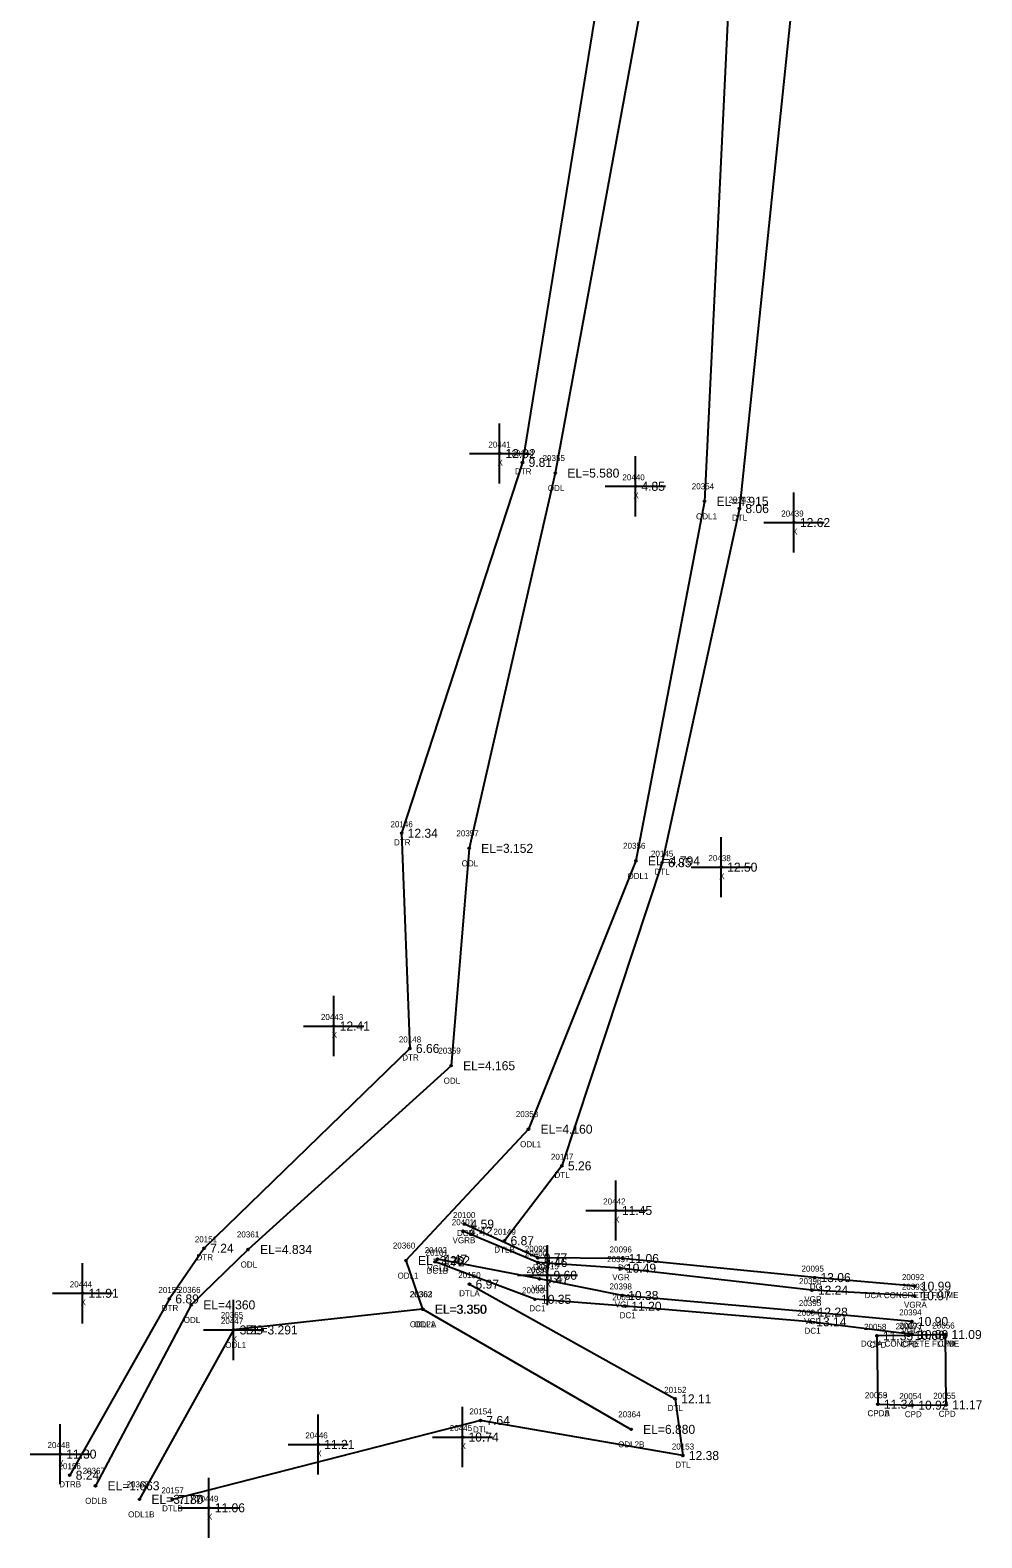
# Model space of a CAD drawing. Extents: x 2072302 to 2072980, y 127650 to 129736.
# Drawn here: x 2072301.6 to 2072459.9, y 128065.3 to 128316.1 of the extents above; entities that cross this region are included whole.
import ezdxf

# ---------------------------------------------------------------- set-up
doc = ezdxf.new("R2010")
doc.units = 0
for name, color, linetype in [('RD_EX_Conc', 7, 'Continuous'), ('RD_EX_Conc_txCode', 7, 'Continuous'), ('RD_EX_H2O', 7, 'Continuous'), ('RD_EX_H2O_txCode', 7, 'Continuous'), ('RD_EX_Misc', 7, 'Continuous'), ('RD_EX_Misc_txCode', 7, 'Continuous'), ('RD_EX_Road', 7, 'Continuous'), ('RD_EX_Road_txCode', 7, 'Continuous'), ('RD_EX_TX_Conc_ELEV', 7, 'Continuous'), ('RD_EX_TX_H2O_ELEV', 7, 'Continuous'), ('RD_EX_TX_Misc_ELEV', 7, 'Continuous'), ('RD_EX_TX_Road_ELEV', 7, 'Continuous'), ('RD_SMD_Locator', 7, 'Continuous')]:
    doc.layers.add(name, color=color, linetype=linetype)

msp = doc.modelspace()

# ---------------------------------------------------------------- linework, layer by layer
at = {"layer": 'RD_EX_Conc'}
for points in [[(2072448.74, 128107.16), (2072432.05, 128108.58), (2072400.16, 128111.76), (2072386.04, 128111.87), (2072373.86, 128117.48)], [(2072448.27, 128099.1), (2072431.34, 128101.24), (2072400.6, 128103.82), (2072385.58, 128104.97), (2072368.98, 128111.22)], [(2072442.59, 128087.52), (2072448.31, 128087.36), (2072453.95, 128087.42), (2072453.82, 128099.11), (2072447.69, 128098.97), (2072442.43, 128098.89), (2072442.59, 128087.52)]]:
    msp.add_lwpolyline(points, dxfattribs=at)
at = {"layer": 'RD_EX_H2O'}
msp.add_line((2072366.96, 128103.32), (2072401.56, 128083.34), dxfattribs=at)
for points in [[(2072402.16, 128559.26), (2072408.19, 128460.51), (2072419.68, 128361.12), (2072413.76, 128237.7), (2072402.36, 128177.9), (2072384.5, 128133.27), (2072364.13, 128111.41), (2072366.88, 128103.31), (2072335.48, 128099.87), (2072319.81, 128071.7)], [(2072403.62, 128560.29), (2072411.45, 128462.26), (2072432.66, 128362.62), (2072419.56, 128236.49), (2072406.7, 128177.6), (2072390.06, 128127.17), (2072380.51, 128114.72)], [(2072394.05, 128557.65), (2072400.51, 128459.22), (2072402.07, 128358.79), (2072383.51, 128244.18), (2072363.41, 128182.49), (2072364.78, 128146.69), (2072330.57, 128113.46), (2072324.79, 128105.03), (2072308.22, 128075.71)], [(2072398.39, 128558.24), (2072402.78, 128459.46), (2072410.6, 128360.44), (2072388.96, 128242.4), (2072374.63, 128179.98), (2072371.63, 128143.83), (2072337.87, 128113.26), (2072328.43, 128104.04), (2072312.51, 128073.95)], [(2072374.7, 128107.49), (2072408.89, 128088.41), (2072410.16, 128078.98), (2072376.5, 128084.82), (2072325.3, 128071.69)]]:
    msp.add_lwpolyline(points, dxfattribs=at)
at = {"layer": 'RD_EX_Misc'}
for p, q in [((2072379.67, 128240.64), (2072379.67, 128250.64)), ((2072374.67, 128245.64), (2072384.67, 128245.64)), ((2072402.27, 128235.2), (2072402.27, 128245.2)), ((2072397.27, 128240.2), (2072407.27, 128240.2)), ((2072428.63, 128229.17), (2072428.63, 128239.17)), ((2072423.63, 128234.17), (2072433.63, 128234.17)), ((2072416.53, 128171.85), (2072416.53, 128181.85)), ((2072411.53, 128176.85), (2072421.53, 128176.85)), ((2072352.11, 128145.43), (2072352.11, 128155.43)), ((2072347.11, 128150.43), (2072357.11, 128150.43)), ((2072399.04, 128114.74), (2072399.04, 128124.74)), ((2072394.04, 128119.74), (2072404.04, 128119.74)), ((2072387.66, 128103.97), (2072387.66, 128113.97)), ((2072310.34, 128100.97), (2072310.34, 128110.97)), ((2072382.66, 128108.97), (2072392.66, 128108.97)), ((2072305.34, 128105.97), (2072315.34, 128105.97)), ((2072335.48, 128094.87), (2072335.48, 128104.87)), ((2072330.48, 128099.87), (2072340.48, 128099.87)), ((2072349.54, 128075.83), (2072349.54, 128085.83)), ((2072373.53, 128077.06), (2072373.53, 128087.06)), ((2072306.65, 128074.22), (2072306.65, 128084.22)), ((2072344.54, 128080.83), (2072354.54, 128080.83)), ((2072368.53, 128082.06), (2072378.53, 128082.06)), ((2072301.65, 128079.22), (2072311.65, 128079.22)), ((2072331.34, 128065.29), (2072331.34, 128075.29)), ((2072326.34, 128070.29), (2072336.34, 128070.29))]:
    msp.add_line(p, q, dxfattribs=at)
at = {"layer": 'RD_EX_Road'}
for points in [[(2072448.68, 128105.56), (2072431.62, 128106.49), (2072399.7, 128110.15), (2072386.07, 128111.1), (2072373.61, 128116.3)], [(2072448.25, 128101.29), (2072431.57, 128102.84), (2072400.08, 128105.61), (2072386.32, 128108.37), (2072369.39, 128111.65)]]:
    msp.add_lwpolyline(points, dxfattribs=at)
at = {"layer": 'RD_SMD_Locator'}
for centre in [(2072379.67, 128245.64), (2072383.51, 128244.18), (2072388.96, 128242.4), (2072402.27, 128240.2), (2072413.76, 128237.7), (2072419.56, 128236.49), (2072428.63, 128234.17), (2072363.41, 128182.49), (2072374.63, 128179.98), (2072402.36, 128177.9), (2072406.7, 128177.6), (2072416.53, 128176.85), (2072352.11, 128150.43), (2072364.78, 128146.69), (2072371.63, 128143.83), (2072384.5, 128133.27), (2072390.06, 128127.17), (2072399.04, 128119.74), (2072373.86, 128117.48), (2072373.61, 128116.3), (2072380.51, 128114.72), (2072330.57, 128113.46), (2072337.87, 128113.26), (2072364.13, 128111.41), (2072368.98, 128111.22), (2072369.39, 128111.65), (2072386.04, 128111.87), (2072386.07, 128111.1), (2072399.7, 128110.15), (2072400.16, 128111.76), (2072374.7, 128107.49), (2072386.32, 128108.37), (2072387.66, 128108.97), (2072432.05, 128108.58), (2072448.74, 128107.16), (2072310.34, 128105.97), (2072324.79, 128105.03), (2072385.58, 128104.97), (2072400.08, 128105.61), (2072431.62, 128106.49), (2072448.68, 128105.56), (2072328.43, 128104.04), (2072366.88, 128103.31), (2072366.96, 128103.32), (2072400.6, 128103.82), (2072431.57, 128102.84), (2072335.48, 128099.87), (2072335.48, 128099.87), (2072431.34, 128101.24), (2072448.25, 128101.29), (2072442.43, 128098.89), (2072447.69, 128098.97), (2072448.27, 128099.1), (2072453.82, 128099.11), (2072408.89, 128088.41), (2072442.59, 128087.52), (2072442.59, 128087.52), (2072448.31, 128087.36), (2072453.95, 128087.42), (2072376.5, 128084.82), (2072373.53, 128082.06), (2072401.56, 128083.34), (2072349.54, 128080.83), (2072306.65, 128079.22), (2072410.16, 128078.98), (2072308.22, 128075.71), (2072312.51, 128073.95), (2072319.81, 128071.7), (2072325.3, 128071.69), (2072331.34, 128070.29)]:
    msp.add_circle(centre, 0.15, dxfattribs=at)

# ---------------------------------------------------------------- texts
at = {"layer": 'RD_EX_Conc_txCode'}
for s, p in [('20100', (2072371.95, 128118.48)), ('DCB', (2072372.61, 128115.48)), ('20101', (2072367.39, 128112.22)), ('20099', (2072383.89, 128112.87)), ('20096', (2072397.97, 128112.76)), ('DC1B', (2072367.56, 128109.22)), ('DC', (2072385.26, 128109.87)), ('DC', (2072399.38, 128109.76)), ('20095', (2072429.89, 128109.58)), ('DC', (2072431.27, 128106.58)), ('20092', (2072446.58, 128108.16)), ('20098', (2072383.42, 128105.97)), ('20097', (2072398.44, 128104.82)), ('DCA CONCRETE FLUME', (2072440.39, 128105.16)), ('DC1', (2072384.63, 128102.97)), ('DC1', (2072399.66, 128101.82)), ('20094', (2072429.18, 128102.24)), ('DC1', (2072430.39, 128099.24)), ('20058', (2072440.28, 128099.89)), ('20057', (2072445.53, 128099.97)), ('20093', (2072446.12, 128100.1)), ('20056', (2072451.64, 128100.11)), ('DC1A CONCRETE FLUME', (2072439.76, 128097.1)), ('CPD', (2072441.18, 128096.89)), ('CPD', (2072446.44, 128096.97)), ('CPD', (2072452.57, 128097.11)), ('20053', (2072440.43, 128088.52)), ('20059', (2072440.43, 128088.52)), ('20054', (2072446.15, 128088.36)), ('20055', (2072451.79, 128088.42)), ('CPDA', (2072440.85, 128085.52)), ('CPDB', (2072440.87, 128085.52)), ('CPD', (2072447.06, 128085.36)), ('CPD', (2072452.7, 128085.42))]:
    msp.add_text(s, height=1, dxfattribs=at).set_placement(p)
at = {"layer": 'RD_EX_H2O_txCode'}
for s, p in [('20144', (2072381.68, 128245.18)), ('20355', (2072386.84, 128244.4)), ('DTR', (2072382.25, 128242.18)), ('ODL', (2072387.71, 128239.4)), ('20354', (2072411.64, 128239.7)), ('20143', (2072417.73, 128237.49)), ('ODL1', (2072412.35, 128234.7)), ('DTL', (2072418.32, 128234.49)), ('20146', (2072361.55, 128183.49)), ('20357', (2072372.51, 128181.98)), ('DTR', (2072362.14, 128180.49)), ('20356', (2072400.22, 128179.9)), ('ODL', (2072373.39, 128176.98)), ('20145', (2072404.86, 128178.6)), ('ODL1', (2072400.95, 128174.9)), ('DTL', (2072405.45, 128175.6)), ('20148', (2072362.94, 128147.69)), ('DTR', (2072363.51, 128144.69)), ('20359', (2072369.51, 128145.83)), ('ODL', (2072370.39, 128140.83)), ('20358', (2072382.39, 128135.27)), ('ODL1', (2072383.1, 128130.27)), ('20147', (2072388.23, 128128.17)), ('DTL', (2072388.82, 128125.17)), ('20151', (2072329.02, 128114.46)), ('20361', (2072336.02, 128115.26)), ('20149', (2072378.68, 128115.72)), ('DTR', (2072329.3, 128111.46)), ('20360', (2072361.95, 128113.41)), ('DTLB', (2072378.8, 128112.72)), ('ODL', (2072336.63, 128110.26)), ('ODL1', (2072362.72, 128108.41)), ('20150', (2072372.82, 128108.49)), ('20155', (2072322.96, 128106.03)), ('20366', (2072326.26, 128106.04)), ('20363', (2072364.74, 128105.31)), ('20362', (2072364.82, 128105.32)), ('DTLA', (2072372.97, 128105.49)), ('DTR', (2072323.52, 128103.03)), ('20365', (2072333.34, 128101.87)), ('ODL', (2072327.18, 128101.04)), ('ODL2A', (2072364.78, 128100.32)), ('ODL1', (2072365.47, 128100.31)), ('ODL1', (2072334.07, 128096.87)), ('20152', (2072407.05, 128089.41)), ('DTL', (2072407.64, 128086.41)), ('20154', (2072374.67, 128085.82)), ('20364', (2072399.41, 128085.34)), ('DTL', (2072375.26, 128082.82)), ('ODL2B', (2072399.39, 128080.34)), ('20153', (2072408.32, 128079.98)), ('20156', (2072306.36, 128076.71)), ('DTL', (2072408.91, 128076.98)), ('DTRB', (2072306.48, 128073.71)), ('20367', (2072310.37, 128075.95)), ('20368', (2072317.67, 128073.7)), ('20157', (2072323.47, 128072.69)), ('ODLB', (2072310.79, 128070.95)), ('ODL1B', (2072317.93, 128068.7)), ('DTLB', (2072323.59, 128069.69))]:
    msp.add_text(s, height=1, dxfattribs=at).set_placement(p)
at = {"layer": 'RD_EX_Misc_txCode'}
for s, p in [('20441', (2072377.83, 128246.64)), ('X', (2072379.35, 128243.64)), ('20440', (2072400.11, 128241.2)), ('X', (2072401.95, 128238.2)), ('20439', (2072426.52, 128235.17)), ('X', (2072428.32, 128232.17)), ('20438', (2072414.41, 128177.85)), ('X', (2072416.21, 128174.85)), ('20443', (2072349.99, 128151.43)), ('X', (2072351.79, 128148.43)), ('20442', (2072396.92, 128120.74)), ('X', (2072398.72, 128117.74)), ('20415', (2072385.82, 128109.97)), ('20444', (2072308.23, 128106.97)), ('X', (2072387.34, 128106.97)), ('X', (2072310.03, 128103.97)), ('20447', (2072333.36, 128100.87)), ('X', (2072335.17, 128097.87)), ('20446', (2072347.4, 128081.83)), ('20445', (2072371.41, 128083.06)), ('20448', (2072304.53, 128080.22)), ('X', (2072349.22, 128078.83)), ('X', (2072373.21, 128080.06)), ('X', (2072306.33, 128077.22)), ('20449', (2072329.22, 128071.29)), ('X', (2072331.03, 128068.29))]:
    msp.add_text(s, height=1, dxfattribs=at).set_placement(p)
at = {"layer": 'RD_EX_Road_txCode'}
for s, p in [('20401', (2072371.74, 128117.3)), ('VGRB', (2072371.87, 128114.3)), ('20402', (2072367.23, 128112.65)), ('20400', (2072383.88, 128112.1)), ('20397', (2072397.58, 128111.15)), ('VGLB', (2072367.67, 128109.65)), ('20399', (2072384.2, 128109.37)), ('VGR', (2072384.81, 128109.1)), ('VGL', (2072385.08, 128106.37)), ('20398', (2072397.97, 128106.61)), ('VGR', (2072398.43, 128108.15)), ('20396', (2072429.48, 128107.49)), ('20393', (2072446.57, 128106.56)), ('20395', (2072429.45, 128103.84)), ('VGR', (2072430.35, 128104.49)), ('VGL', (2072398.84, 128103.61)), ('20394', (2072446.13, 128102.29)), ('VGRA', (2072446.93, 128103.56)), ('VGL', (2072430.32, 128100.84)), ('VGLA', (2072446.52, 128099.29))]:
    msp.add_text(s, height=1, dxfattribs=at).set_placement(p)
at = {"layer": 'RD_EX_TX_Conc_ELEV'}
for s, p in [('4.59', (2072374.86, 128116.73)), ('9.77', (2072387.04, 128111.12)), ('11.06', (2072401.16, 128111.01)), ('4.72', (2072369.98, 128110.47)), ('13.06', (2072433.05, 128107.83)), ('10.99', (2072449.74, 128106.41)), ('10.35', (2072386.58, 128104.22)), ('11.20', (2072401.6, 128103.07)), ('13.14', (2072432.34, 128100.49)), ('11.35', (2072443.43, 128098.14)), ('10.88', (2072448.69, 128098.22)), ('10.89', (2072449.27, 128098.35)), ('11.09', (2072454.82, 128098.36)), ('11.34', (2072443.59, 128086.77)), ('11.34', (2072443.59, 128086.77)), ('10.92', (2072449.31, 128086.61)), ('11.17', (2072454.95, 128086.67))]:
    msp.add_text(s, height=1.5, dxfattribs=at).set_placement(p)
at = {"layer": 'RD_EX_TX_H2O_ELEV'}
for s, p in [('9.81', (2072384.51, 128243.43)), ('EL=5.580', (2072390.96, 128241.65)), ('EL=4.915', (2072415.76, 128236.95)), ('8.06', (2072420.56, 128235.74)), ('12.34', (2072364.41, 128181.74)), ('EL=3.152', (2072376.63, 128179.23)), ('EL=4.794', (2072404.36, 128177.15)), ('6.85', (2072407.7, 128176.85)), ('6.66', (2072365.78, 128145.94)), ('EL=4.165', (2072373.63, 128143.08)), ('EL=4.160', (2072386.5, 128132.52)), ('5.26', (2072391.06, 128126.42)), ('6.87', (2072381.51, 128113.97)), ('7.24', (2072331.57, 128112.71)), ('EL=4.834', (2072339.87, 128112.51)), ('EL=3.262', (2072366.13, 128110.66)), ('6.97', (2072375.7, 128106.74)), ('6.89', (2072325.79, 128104.28)), ('EL=4.360', (2072330.43, 128103.29)), ('EL=3.350', (2072368.88, 128102.56)), ('EL=3.350', (2072368.96, 128102.57)), ('EL=3.291', (2072337.48, 128099.12)), ('12.11', (2072409.89, 128087.66)), ('7.64', (2072377.5, 128084.07)), ('EL=6.880', (2072403.56, 128082.59)), ('12.38', (2072411.16, 128078.23)), ('8.24', (2072309.22, 128074.96)), ('EL=1.663', (2072314.51, 128073.2)), ('EL=3.180', (2072321.81, 128070.95)), ('7.77', (2072326.3, 128070.94))]:
    msp.add_text(s, height=1.5, dxfattribs=at).set_placement(p)
at = {"layer": 'RD_EX_TX_Misc_ELEV'}
for s, p in [('12.92', (2072380.67, 128244.89)), ('4.85', (2072403.27, 128239.45)), ('12.62', (2072429.63, 128233.42)), ('12.50', (2072417.53, 128176.1)), ('12.41', (2072353.11, 128149.68)), ('11.45', (2072400.04, 128118.99)), ('9.60', (2072388.66, 128108.22)), ('11.91', (2072311.34, 128105.22)), ('3.29', (2072336.48, 128099.12)), ('10.74', (2072374.53, 128081.31)), ('11.30', (2072307.65, 128078.47)), ('11.21', (2072350.54, 128080.08)), ('11.06', (2072332.34, 128069.54))]:
    msp.add_text(s, height=1.5, dxfattribs=at).set_placement(p)
at = {"layer": 'RD_EX_TX_Road_ELEV'}
for s, p in [('4.42', (2072374.61, 128115.55)), ('4.47', (2072370.39, 128110.9)), ('9.46', (2072387.07, 128110.35)), ('10.49', (2072400.7, 128109.4)), ('9.47', (2072387.32, 128107.62)), ('12.24', (2072432.62, 128105.74)), ('10.38', (2072401.08, 128104.86)), ('10.97', (2072449.68, 128104.81)), ('12.28', (2072432.57, 128102.09)), ('10.90', (2072449.25, 128100.54))]:
    msp.add_text(s, height=1.5, dxfattribs=at).set_placement(p)

doc.saveas('drawing.dxf')
